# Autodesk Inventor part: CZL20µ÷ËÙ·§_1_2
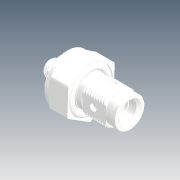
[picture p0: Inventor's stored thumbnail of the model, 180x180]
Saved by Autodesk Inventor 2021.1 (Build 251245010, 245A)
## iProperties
Created: 2021-05
Part Number: CZL20µ÷ËÙ·§_1_2
Material: Ogólny
Document SubType Name: Modeling
Designer: user
Density: 1 g/cm^3
Appearance: Domyślna
Author: user
Revision Number: ÈÎºÎ
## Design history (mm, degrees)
feature "NONE"
feature "Złożony1"
node "Bryła1"
body "Srf1"
